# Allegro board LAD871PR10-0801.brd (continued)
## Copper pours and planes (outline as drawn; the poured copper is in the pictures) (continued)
AUD_SPK_L+_C on BOTTOM (solid shape): 80.64,6.48 80.83,6.48 80.83,5.46 79.75,5.46 79.43,5.78 79.43,6.38 78.61,7.21 77.29,7.21 77.17,7.33 77.17,7.78 77.29,7.9 79.21,7.9
AUD_SPK_L- on TOP (solid shape): 93.57,4.62 93.54,4.6 91.32,4.6 91.14,4.77 91.14,5.55 91.21,5.61 93.57,5.61
AUD_SPK_L- on TOP (solid shape): 184.99,10.39 184.99,8.6 184.93,8.53 183.72,8.53 183.6,8.65 183.6,10.31 183.78,10.49 184.89,10.49
AUD_SPK_L- on BOTTOM (solid shape): 183.48,11.25 183.48,10.78 183.8,10.46 184.28,10.46 184.36,10.39 184.36,9.6 184.21,9.45 183.78,9.45 182.99,10.24 182.99,11.24 183.02,11.28 183.46,11.28
AUD_SPK_L-_C on TOP (solid shape): 81.34,8.89 81.34,3.94 81.67,3.61 84.21,3.61 85.81,5.21 87.56,5.21 87.69,5.33 88.86,5.33 88.88,5.35 89.26,5.35 89.72,5.81 90.77,5.81 90.88,5.7 90.88,4.72 90.83,4.67 88.32,4.67 87.42,3.76 86.62,3.76 85.46,2.6 81.08,2.6 80.13,3.56 80.13,8.89 80.26,9.02 81.21,9.02
AUD_SPK_L-_C on BOTTOM (solid shape): 81.27,9.21 81.27,8.45 81.08,8.25 77.27,8.25 77.15,8.38 77.15,8.89 77.27,9.02 78.54,9.02 78.86,9.33 81.15,9.33
AUD_SPK_R+ on TOP (solid shape): 92.38,9.69 92.26,9.58 91.2,9.58 91.09,9.69 91.09,10.91 91.27,11.08 92.38,11.08
AUD_SPK_R+ on TOP (solid shape): 182.05,11.18 182.05,11 181.9,10.85 181.74,10.85 181.39,10.49 181.38,10.49 181.38,10.25 180.57,9.44 180.12,9.44 179.53,10.03 179.53,10.18 180.68,11.33 181.9,11.33
AUD_SPK_R+ on BOTTOM (solid shape): 182.66,12.5 182.66,12.27 182.07,11.68 182.07,10.97 181.57,10.46 181.26,10.46 181.13,10.59 181.13,10.85 181.69,11.4 181.69,11.63 182.58,12.52 182.63,12.52
AUD_SPK_R+_C on TOP (solid shape): 87.69,11.11 87.69,11.05 90.81,11.05 90.95,10.92 90.95,9.66 90.88,9.6 89.91,9.6 89.47,10.04 89.46,10.04 89.41,10.1 85.94,10.1 85.62,10.41 83.75,10.41 82.99,9.65 82.99,4.89 83.11,4.76 83.11,4 82.99,3.87 82.16,3.87 81.84,4.19 81.84,10.16 83.11,11.43 87.37,11.43
AUD_SPK_R+_C on BOTTOM (solid shape): 78.75,5.75 78.75,5.3 79.17,4.89 82.99,4.89 83.11,4.76 83.11,4 83.01,3.9 78.76,3.9 77.17,5.49 77.17,5.68 77.36,5.87 78.63,5.87
AUD_SPK_R- on TOP (solid shape): 93.57,8.25 93.54,8.23 91.2,8.23 91.03,8.39 91.03,9.05 91.23,9.25 93.57,9.25
AUD_SPK_R- on TOP (solid shape): 182.05,10.16 182.05,8.81 181.2,7.96 180.82,7.96 180.14,8.64 180.14,8.83 181.6,10.29 181.92,10.29
AUD_SPK_R- on BOTTOM (solid shape): 182.71,10.97 182.71,10.39 181.69,9.37 181.36,9.37 181.24,9.5 181.24,9.73 182.19,10.69 182.19,10.91 182.2,10.92 182.2,10.96 182.26,11.02 182.65,11.02
AUD_SPK_R-_C on TOP (solid shape): 90.86,9.11 90.86,8.31 90.68,8.13 85.78,8.13 84.51,6.86 83.37,6.86 83.31,6.92 83.31,7.3 84.64,8.64 84.83,8.64 85.38,9.19 90.78,9.19
AUD_SPK_R-_C on BOTTOM (solid shape): 83.5,7.75 84.19,7.75 84.38,7.56 84.38,6.98 84.19,6.79 83.05,6.79 81.91,7.94 81.91,8.32 82.92,8.32
AUD_SPK_R-_C on BOTTOM (solid shape): 77.08,6.86 78.61,6.86 78.73,6.73 78.73,6.35 78.61,6.22 77.34,6.22 77.15,6.03 76.45,6.03 75.75,6.73 75.75,7.24 76.7,7.24
BST2_VGA on BOTTOM (solid shape): 162.36,105.15 162.36,105.02 163.05,104.33 163.06,104.33 163.19,104.2 164.65,104.2 164.65,103.31 163.33,103.31 161.7,104.95 161.49,104.95 161.34,105.1 161.34,105.19 161.39,105.24 162.27,105.24
BST_1.2V on TOP (solid shape): 61.97,20.64 63.43,20.64 63.43,20 61.78,20 60.95,20.83 59.81,20.83 59.81,21.02 61.59,21.02
BST_1.2V_R on TOP (solid shape): 63.43,17.53 63.37,17.46 62.86,17.46 62.79,17.53 62.79,18.29 62.54,18.54 62.54,19.24 63.43,19.24
BST_3V on BOTTOM (solid shape): 31.12,37.52 32.85,37.52 32.92,37.44 32.92,37.34 32.77,37.19 29.87,37.19 29.8,37.25 29.8,38.27 29.87,38.33 30.31,38.33
BST_5V on BOTTOM (solid shape): 42.63,37.69 44.56,37.69 44.61,37.64 44.61,37.49 44.35,37.24 41.46,37.24 41.41,37.29 41.41,38.18 41.46,38.23 42.09,38.23
BST_+1.5VGPU on BOTTOM (solid shape): 132.84,138.68 130.61,138.68 130.61,138.94 131.57,138.94 132.2,139.57 132.84,139.57
BST_+1.5VGPU_R on BOTTOM (solid shape): 133.72,140.08 134.23,139.57 134.23,138.68 133.6,138.68 133.6,139.52 133.22,139.9 133.22,140.53 133.72,140.53
BST_+1VALW on BOTTOM (solid shape): 128.52,123.76 129.85,123.76 129.91,123.7 129.91,123.57 129.85,123.51 127.18,123.51 127.12,123.57 127.12,124.46 127.18,124.52 127.76,124.52
BST_+1VALW_R on BOTTOM (solid shape): 126.42,124.46 126.42,123.62 126.56,123.48 126.71,123.48 126.93,123.25 126.93,122.55 126.36,122.55 126.36,122.94 125.72,123.57 125.72,124.46 125.79,124.52 126.36,124.52
BST_+VCCEOPIO on BOTTOM (solid shape): 38.47,53.28 38.47,52.96 39.36,52.07 39.36,50.36 39.3,50.29 38.47,50.29 38.41,50.36 38.41,52.32 37.59,53.15 37.59,53.28 37.65,53.34 38.41,53.34
BST_R_+VCCEOPIO on BOTTOM (solid shape): 40.38,49.09 40.19,48.89 38.41,48.89 38.41,49.53 38.47,49.59 40.38,49.59
C0_1.0VS_VCCOPCP on BOTTOM (solid shape): 34.4,57.14 34.4,56.48 34.48,56.4 36.36,56.4 36.82,55.94 36.82,54.86 36.76,54.8 36.7,54.8 36.57,54.93 36.57,55.63 36.25,55.94 35.3,55.94 35.11,56.13 35.1,56.13 35.06,56.17 34.13,56.17 33.7,56.6 33.7,57.19 33.71,57.2 34.34,57.2
C1_1.0VS_VCCOPCP on BOTTOM (solid shape): 33.45,57.09 33.46,57.09 33.56,56.98 33.56,56.44 33.68,56.44 34.08,56.05 35.01,56.05 35.36,55.69 36.32,55.69 36.38,55.63 36.38,54.93 36.25,54.8 35.74,54.8 34.92,55.63 34.91,55.63 34.84,55.69 34.03,55.69 33.46,56.26 32.69,56.26 32.6,56.36 32.6,57.07 32.71,57.18 33.35,57.18
CORE_SNUB on TOP (solid shape): 111.75,122.9 111.75,120.4 111.66,120.3 110.58,120.3 110.55,120.33 110.55,123 110.58,123.03 111.63,123.03
CORE_SW on TOP (solid shape): 114.48,122.43 114.48,120.4 114.36,120.27 113.21,120.27 113.09,120.4 113.09,122.55 113.15,122.62 114.29,122.62
CORE_SW on BOTTOM (solid shape): 115.25,122.36 115.25,119.04 113.34,119.04 113.34,120.02 112.45,120.02 112.45,119.05 110.61,119.05 110.61,122.24 111.74,123.37 111.74,123.55 111.8,123.62 113.99,123.62
CPU_B+ on TOP (solid shape): 119.3,128.09 119.3,126.45 119.22,126.36 116.95,126.36 116.93,126.38 116.93,126.62 116.87,126.68 115.07,126.68 115,126.75 115,128.81 114.98,128.83 115.75,129.6 117.79,129.6
CPU_B+ on TOP (solid shape): 109.55,129.66 109.55,127.78 109.29,127.51 109.29,127.35 109.28,127.34 109.26,127.23 109.28,127.13 109.29,127.12 109.29,126.78 109.55,126.51 109.55,125.96 109.5,125.91 108.05,125.91 107.95,126 107.95,129.61 108.11,129.76 109.46,129.76
CPU_B+ on BOTTOM (solid shape): 111.44,131.64 111.44,129.86 109.59,128.02 109.59,126.85 109.91,126.54 110.4,126.54 110.6,126.75 111.31,126.75 111.35,126.79 111.35,127.33 111.38,127.36 114.01,127.36 115.25,128.59 115.25,128.78 116.13,129.67 116.13,130.62 116.33,130.81 117.47,130.81 117.47,129.48 119.21,127.73 119.21,126.38 119.19,126.35 118.6,126.35 118.14,126.81 115.59,126.81 114.6,125.82 112.32,125.82 112.31,125.82 111.41,125.82 111.37,125.85 111.37,126.26 111.26,126.37 110.58,126.37 110.31,126.1 110.31,125.58 110.18,125.45 105.84,125.45 105.53,125.76 105.53,130.17 107.05,131.7 111.37,131.7
CPU_B+ on IN2 (solid shape): outline of 176 points within 107.5,124.27 118.1,129.73
CS_1.2V on TOP (solid shape): 58.73,19.75 58.73,18.48 59.37,17.84 59.37,16.76 58.73,16.76 58.73,17.34 58.54,17.53 58.54,19.74 58.6,19.81 58.67,19.81
DCBAT_CAM on BOTTOM (solid shape): 77.59,168.72 77.97,168.72 78.67,168.02 81.91,168.02 82.48,167.45 82.48,165.54 82.35,165.42 81.72,165.42 81.65,165.48 81.65,166.56 81.15,167.07 78.29,167.07 77.5,167.86 77.5,167.99 77.44,168.05 75.84,168.05 75.75,168.14 75.75,168.67 75.76,168.68 75.75,168.69 75.75,168.78 75.88,168.91 77.4,168.91
DCBATOUT_LCD on BOTTOM (solid shape): outline of 138 points within 74.8,160.56 81.46,168.02
EC_AGND on IN1 (solid shape): outline of 112 points within 182.55,57.98 186.62,66.06
EN_0.6VSP on TOP (solid shape): 55.56,23.24 56.44,22.35 56.44,21.65 56.66,21.44 57.46,21.44 57.51,21.39 57.52,21.39 57.52,21.27 57.46,21.21 56.38,21.21 56.06,21.53 56.06,22.16 55.43,22.8 55.05,22.8 55.05,24.26 55.56,24.26
EN_1.2V on TOP (solid shape): 55.56,21.59 56.13,21.02 57.46,21.02 57.52,20.95 57.52,20.89 57.46,20.83 55.75,20.83 55.56,21.02 55.05,21.02 55.05,22.48 55.56,22.48
EN_1.8VALW on BOTTOM (solid shape): 174.79,26.86 174.79,26.31 175.13,25.97 175.76,25.97 175.82,25.91 175.82,25.46 175.76,25.4 174.3,25.4 174.27,25.43 174.27,25.93 174.05,26.16 173.28,26.16 173.22,26.23 173.22,26.67 173.28,26.73 174.05,26.73 174.24,26.92 174.72,26.92
EN_2.5V on BOTTOM (solid shape): 60.64,29.46 60.64,29.08 60.51,28.96 56.89,28.96 56.89,29.46 57.02,29.59 60.51,29.59
EN_+1VALW on BOTTOM (solid shape): 133.28,127.17 133.11,127.01 133.11,125.5 132.93,125.32 132.17,125.32 132.14,125.35 132.14,125.48 132.14,125.48 132.14,125.53 132.33,125.72 132.33,126.56 131.69,127.19 131.69,127.76 133.28,127.76
EN_+VCCEOPIO on BOTTOM (solid shape): 37.01,56.58 37.33,56.26 37.33,54.86 37.27,54.8 37.14,54.8 37.08,54.86 37.08,55.88 36.43,56.53 34.59,56.53 34.53,56.59 34.53,57.05 34.57,57.09 37.01,57.09
FAN_VCC1 on BOTTOM (solid shape): 100.22,146.02 100.22,137.66 99.87,137.66 99.48,137.82 99.21,137.5 99.17,137.44 99.1,137.41 97.08,137.41 94.37,134.7 93.12,134.7 92.78,135.04 91.92,137.16 91.92,137.28 92.14,137.51 92.37,137.51 92.49,137.38 92.99,136.39 93.24,136.14 94.28,136.14 97.03,138.89 98.75,138.89 99.07,139.22 99.07,145.57 98.76,145.89 97.17,145.89 97.04,146.02 97.04,146.46 97.23,146.65 99.58,146.65
FB_1.2V on TOP (solid shape): 56.57,23.24 57.46,22.35 57.46,21.65 56.7,21.65 56.64,21.72 56.64,22.54 56.06,23.11 56.06,24.38 55.81,24.64 55.05,24.64 55.05,25.21 55.81,25.21 56,25.4 56.57,25.4
GPU_B+ on TOP (solid shape): 62.42,47.39 62.42,45.82 60.7,44.11 60.7,41.44 60.99,41.15 64.51,41.15 64.83,40.83 66.68,40.83 66.74,40.77 69.84,40.77 69.97,40.64 69.97,38.11 69.92,37.94 69.95,37.77 69.7,37.51 59.94,37.51 59.94,37.5 59.94,36.97 59.49,36.97 59.49,37.5 58.74,37.5 58.74,36.97 58.29,36.97 58.29,37.5 58.28,37.5 58.28,37.51 57.59,37.51 57.59,39.31 57.97,39.69 57.97,43.39 54.67,46.69 54.67,47.24 54.84,47.42 59.03,47.42 59.12,47.51 62.3,47.51
GPU_B+ on BOTTOM (solid shape): outline of 104 points within 54.51,36.44 70.9,47.51
GT_SNUB1 on TOP (solid shape): 71.24,47.24 71.24,44.95 71.14,44.84 68.9,44.84 68.78,44.97 68.78,47.24 68.88,47.34 71.13,47.34
GT_SNUB2 on TOP (solid shape): 60.2,53.77 60.2,51.74 59.47,51 58.4,51 58.25,51.16 58.25,53.72 58.4,53.87 60.1,53.87
GT_SW1 on TOP (solid shape): 67.32,47.25 67.32,44.38 67.19,44.25 66.33,44.25 66.22,44.36 66.22,47.32 66.27,47.37 67.2,47.37
GT_SW1 on BOTTOM (solid shape): 68.07,47.46 68.07,46.49 68.95,46.49 68.95,47.45 68.98,47.47 70.81,47.47 70.99,47.29 70.99,44.58 69.65,43.24 69.65,43.07 69.51,42.93 67.62,42.93 67.54,43 67.54,43.95 67.31,44.19 65.91,44.19 65.53,44.57 65.53,47.12 65.92,47.51 68.01,47.51
GT_SW2 on TOP (solid shape): 57.46,54.08 57.46,51.97 55.76,51.97 55.63,52.1 55.63,54.1 55.82,54.29 57.24,54.29
GT_SW2 on BOTTOM (solid shape): 57.82,53.25 58.63,53.25 58.63,54.23 61.99,54.23 62.16,54.06 62.16,49.9 62.01,49.75 60.06,49.75 60.03,49.78 60.03,50.98 59.5,51.5 58.16,51.5 58.16,51.51 56.11,51.51 55.56,52.07 55.56,54.07 55.71,54.23 57.82,54.23
HDMI_PLL_GND on TOP (solid shape): 25.65,77.28 25.65,74.17 25.9,73.91 28,73.91 28.5,74.42 29.46,74.42 29.71,74.17 29.71,73.41 29.33,73.02 26.79,73.02 25.58,71.82 25.01,71.82 24.95,71.88 24.95,77.28 25.08,77.41 25.52,77.41
IR_GND on BOTTOM (solid shape): 93.5,166.45 93.5,163.07 93.88,162.69 93.88,160.66 93.83,160.6 92.87,160.6 92.59,160.88 92.59,166.4 92.74,166.55 93.4,166.55
KB_BL_CTRL# on TOP (solid shape): 189.16,126.94 189.16,126.36 189.73,125.79 190.74,125.79 190.75,125.8 190.77,125.77 191.52,125.77 192.55,124.74 192.55,124.49 192.48,124.43 189.32,124.43 188.08,125.67 188.08,126.05 187.64,126.49 187.64,126.94 187.89,127.19 188.91,127.19
LANGND on BOTTOM (solid shape): 18.4,162.52 18.4,161.34 18.28,161.23 16.06,161.23 16,161.16 15.11,161.16 15.11,162.18 15.53,162.6 18.32,162.6
LCDVDD on BOTTOM (solid shape): 81.29,156.35 82.66,156.35 82.92,156.09 82.92,155.52 82.67,155.28 79.63,155.28 79.43,155.47 79.43,156.34 79.62,156.53 81.11,156.53
LCDVDD_LCD on TOP (solid shape): 80.12,158.11 81.37,158.11 81.64,157.84 81.64,156.92 80.84,156.11 79.53,156.11 79.37,156.27 79.37,156.46 78.67,157.16 78.67,158.18 78.8,158.31 79.93,158.31
LCDVDD_LCD on BOTTOM (solid shape): 84.45,166.37 84.45,165.42 82.85,163.82 82.81,163.85 82.27,163.81 82.4,163.28 82.45,163.2 82.41,163.11 82.26,162.73 82.56,162.46 82.61,162.46 82.61,160.53 81.62,159.54 81.62,158.9 81.26,158.54 81.26,158.22 81.48,158 81.62,158 81.62,157.38 81.39,157.15 79.51,157.15 79.38,157.28 79.38,160.55 79.53,160.7 79.53,161.09 80.7,162.26 80.83,162.53 80.7,162.81 80.7,164.06 81.4,164.77 81.48,164.8 81.55,164.76 81.97,164.68 82.17,165.05 82.2,165.13 82.27,165.16 82.86,165.16 83.11,165.42 83.11,166.37 83.24,166.5 84.32,166.5
LDO_+1.5VGPU on TOP (solid shape): 128.83,140.02 128.71,139.89 127.88,139.89 127.76,140.02 127.76,140.84 127.88,140.97 128.83,140.97
LDO_+1.5VGPU on BOTTOM (solid shape): 129.09,140.46 129.09,139.13 128.96,139 128.45,139 128.33,139.13 128.33,139.51 127.88,139.95 127.88,140.46 128.07,140.65 128.9,140.65
LDO_+1VALW on BOTTOM (solid shape): 132.58,122.81 134.55,122.81 134.55,122.17 131.76,122.17 131.34,122.59 131.34,123.34 131.44,123.44 131.95,123.44
LG1_VGA on TOP (solid shape): 170.61,104.67 170.61,103.8 170.48,103.67 169.01,103.67 168.74,103.94 168.74,104.69 168.93,104.88 170.4,104.88
LG1_VGA on BOTTOM (solid shape): 170.04,109.07 170.04,108.1 169.92,107.98 168.81,107.98 168.74,108.05 168.74,109.04 168.9,109.2 169.91,109.2
LG1_VGA on BOTTOM (solid shape): 163.88,107.83 163.88,107.52 163.79,107.43 161.39,107.43 161.34,107.49 161.34,107.59 161.39,107.64 162.68,107.64 162.93,107.89 163.82,107.89
LG1_VGA on IN2 (solid shape): 170.6,109.87 170.6,107.4 170.95,107.05 170.95,103.86 170.66,103.57 169.96,103.57 169.78,103.75 169.78,106.47 169.35,106.9 164.49,106.9 163.95,107.45 162.9,107.45 162.82,107.54 162.82,107.79 162.93,107.9 168.66,107.9 168.74,107.99 168.74,109.49 168.73,109.5 168.73,110.07 168.9,110.24 170.23,110.24
LG2_VGA on TOP (solid shape): 170.11,98.64 170.11,97.7 169.95,97.53 169,97.53 168.74,97.79 168.74,98.75 168.88,98.89 169.85,98.89
LG2_VGA on BOTTOM (solid shape): 170.04,103.16 170.04,102.11 169.89,101.96 168.83,101.96 168.74,102.05 168.74,103.14 168.86,103.27 169.93,103.27
LG2_VGA on BOTTOM (solid shape): 162.48,106.44 162.66,106.33 162.86,106.34 162.87,106.34 163.81,106.34 163.91,106.24 163.91,106.01 163.78,105.89 162.94,105.89 162.59,106.24 161.39,106.24 161.34,106.29 161.34,106.39 161.39,106.44
LG2_VGA on IN2 (solid shape): 165.46,105.99 169.22,105.99 169.22,105.98 169.53,105.67 169.53,103.48 169.98,103.02 169.98,97.58 169.94,97.54 168.99,97.54 168.84,97.69 168.84,105.03 168.65,105.23 165.03,105.23 164.37,105.89 162.94,105.89 162.84,105.99 162.84,106.24 162.94,106.34 163.31,106.34 163.46,106.5 164.95,106.5
LG_1.2V on TOP (solid shape): 60.64,18.86 60.64,18.41 60.51,18.29 60.32,18.29 59.68,18.92 59.37,18.92 59.3,18.99 59.3,19.75 59.37,19.81 59.68,19.81
LG_1.2V on BOTTOM (solid shape): 68.51,15.41 68.51,14.35 68.42,14.26 67.45,14.26 67.3,14.41 67.3,15.34 67.39,15.43 67.56,15.43 67.56,15.43 68.48,15.43
LG_1.2V on IN2 (solid shape): 60.89,18.48 60.89,17.46 60.32,17.46 60.19,17.59 60.19,18.16 59.68,18.67 59.68,19.11 59.81,19.24 60.13,19.24
LG_1.2V on IN2 (solid shape): 67.94,15.3 67.94,14.29 67.49,13.84 66.67,13.84 66.35,14.16 66.35,14.48 66.41,14.54 66.54,14.54 67.43,15.43 67.81,15.43
LGATE_CHG on TOP (solid shape): 125.41,162.12 125.41,161.29 125.28,161.16 124.39,161.16 124.14,161.42 124.14,162.12 124.26,162.24 125.28,162.24
LGATE_CHG on BOTTOM (solid shape): 114.14,158.72 114.14,158.45 114.04,158.35 111.75,158.35 111.7,158.39 111.7,158.55 112.94,158.55 113.19,158.8 114.06,158.8
LGATE_CHG on IN1 (solid shape): 125.41,162.18 125.41,161.67 125.15,161.42 122.99,161.42 122.99,162.43 125.15,162.43
LGATE_CHG on IN1 (solid shape): 116.26,159 114.67,159 114.04,158.37 113.15,158.37 113.02,158.5 113.02,158.69 113.21,158.88 113.59,158.88 114.36,159.64 114.61,159.64 114.99,160.02 116.26,160.02
LP#_+VCCEOPIO on BOTTOM (solid shape): 37.9,57.02 37.9,54.93 37.84,54.86 37.65,54.86 37.59,54.93 37.59,56.26 37.27,56.58 37.27,57.02 37.33,57.09 37.84,57.09
LX1_VGA on TOP (solid shape): 179.51,114.17 179.51,104.48 179.1,104.07 170.95,104.07 170.74,104.29 170.74,104.98 170.5,105.22 170.5,109.06 170.79,109.35 175.32,109.35 175.7,109.73 175.7,110.36 175.44,110.62 174.43,110.62 174.05,111 174.05,114.81 174.3,115.06 178.62,115.06
LX1_VGA on BOTTOM (solid shape): 164.97,108.46 164.97,107.95 164.9,107.89 164.39,107.89 164.2,108.08 162.91,108.08 162.68,107.84 161.39,107.84 161.34,107.89 161.34,107.99 161.39,108.04 162.49,108.04 162.96,108.52 163.44,108.52 163.51,108.58 164.84,108.58
LX1_VGA on BOTTOM (solid shape): 179.51,113.79 179.51,109.16 179.09,108.74 177.78,108.74 177.74,108.7 177.74,107.94 177.77,107.91 179.2,107.91 179.5,107.62 179.5,104.5 179.07,104.07 170.86,104.07 170.72,104.2 170.72,104.69 170.5,104.91 170.5,109.01 170.72,109.22 175.06,109.22 175.55,109.71 175.55,110.48 176.12,111.05 176.12,111.29 175.84,111.57 175.49,111.57 175.27,111.34 174.11,111.34 173.91,111.55 173.91,114.83 174.13,115.06 178.24,115.06
LX1_VGA on IN2 (solid shape): 176.73,112.17 176.73,111.41 176.61,111.28 172.8,111.28 172.8,112.29 176.61,112.29
LX1_VGA on IN2 (solid shape): 164.74,109.62 164.74,108.09 164.68,108.03 163.74,108.03 163.64,108.04 163.55,108.03 163.14,108.03 163.04,108.05 162.95,108.03 162.88,108.03 162.82,107.98 162.66,107.98 162.56,108.07 162.56,108.53 162.6,108.61 162.7,108.63 162.89,108.62 163.06,108.71 163.09,108.73 163.13,108.71 163.74,108.97 163.13,109.22 163.09,109.21 163.06,109.22 162.86,109.32 162.64,109.28 162.63,109.27 162.56,109.27 162.56,109.35 162.72,109.51 162.72,109.74 162.72,109.75 164.61,109.75
LX2_VGA on TOP (solid shape): 179.51,103.12 179.51,95 179.13,94.61 174.61,94.61 174.31,94.91 174.31,97.12 173.48,97.95 170.66,97.95 170.47,98.13 170.47,102.85 171.13,103.5 179.13,103.5
LX2_VGA on BOTTOM (solid shape): 162.88,105.76 164.37,105.76 164.4,105.73 164.9,105.73 165.11,105.52 165.11,104.74 165.05,104.68 164.19,104.68 163.67,105.2 163.45,105.2 163.35,105.3 162.98,105.3 162.45,105.83 161.39,105.83 161.34,105.89 161.34,105.99 161.39,106.04 162.6,106.04
LX2_VGA on BOTTOM (solid shape): 179.44,103 179.44,100.38 179.16,100.1 177.77,100.1 177.75,100.08 177.75,99.32 177.8,99.27 179.12,99.27 179.51,98.88 179.51,95 178.87,94.36 175.66,94.36 175.35,94.05 175.35,93.6 175.09,93.34 174.15,93.34 173.91,93.58 173.91,97.57 173.48,98.01 170.56,98.01 170.48,98.09 170.48,102.86 171.13,103.5 178.93,103.5
LX2_VGA on IN1 (solid shape): 176.73,103.48 176.73,102.47 176.54,102.29 174.86,102.29 174.76,102.38 174.76,103.56 174.9,103.7 176.51,103.7
LX2_VGA on IN1 (solid shape): 164.89,105.16 164.9,105.16 164.9,104.4 164.57,104.4 163.81,105.16 163.62,105.16 163.49,105.29 162.93,105.29 162.84,105.38 162.84,105.66 162.93,105.75 164.3,105.75
LX_1.2V on TOP (solid shape): 60.64,20.13 60.64,19.88 62.41,18.1 62.41,17.53 61.84,17.53 61.84,17.91 59.75,20 59.75,20.13 59.81,20.19 60.57,20.19
LX_1.2V on BOTTOM (solid shape): 74.61,24.26 74.61,16.13 74.1,15.62 67.49,15.62 67.3,15.81 67.3,16.57 67.43,16.7 70.92,16.7 71.37,17.14 71.37,19.77 72.32,20.73 72.32,24.26 72.45,24.38 74.48,24.38
LX_1.2V on IN2 (solid shape): 67.81,16.57 67.81,15.75 67.68,15.62 67.3,15.62 67.11,15.81 66.35,15.81 66.35,16.57 66.48,16.7 67.68,16.7
LX_1.2V on IN2 (solid shape): 61.27,19.24 61.46,19.24 62.1,18.61 62.1,18.29 61.4,18.29 61.21,18.48 61.21,18.54 60.25,19.49 60.25,19.75 60.38,19.88 60.64,19.88
LX_1.8VALW on BOTTOM (solid shape): 173.86,29.97 173.86,27.5 173.54,27.18 172.71,27.18 172.46,26.92 172.46,26.23 172.4,26.16 171.76,26.16 171.7,26.23 171.7,26.73 171.13,27.3 167.57,27.3 167.57,29.02 167.82,29.27 169.98,29.27 170.87,30.16 173.67,30.16
LX_3V on BOTTOM (solid shape): 32.87,40.49 32.94,40.46 33.01,40.44 33.03,40.44 33.25,40.21 33.25,39.45 33.2,39.4 32.98,39.4 32.93,39.45 32.29,39.45 32.24,39.5 32.24,40.36 32.37,40.49
LX_3V on BOTTOM (solid shape): 33.76,37.16 33.76,36.27 33.76,36.27 33.76,34.57 33.94,34.39 35.11,34.39 35.19,34.32 35.19,32.59 35.06,32.46 28.17,32.46 27.87,32.77 27.87,35.05 28,35.18 28.82,35.18 29.46,35.81 29.46,36.96 29.52,37.02 29.71,37.02 29.72,37.03 32.82,37.03 33.05,37.26 33.66,37.26
LX_5V on BOTTOM (solid shape): 44.94,40.43 44.94,39.62 44.86,39.55 44.66,39.55 44.58,39.62 43.95,39.62 43.8,39.78 43.8,40.49 44.02,40.72 44.66,40.72
LX_5V on BOTTOM (solid shape): 45.42,37.34 45.42,34.71 46.22,33.91 47.94,33.91 48.04,33.81 48.04,32.23 47.94,32.13 41.11,32.13 40.82,32.42 40.82,35.81 41.01,36 41.01,36.66 41.33,36.98 44.3,36.98 44.74,37.41 45.35,37.41
LX_+1.5VGPU on TOP (solid shape): 131.25,139.7 131.25,136.08 131.06,135.89 130.49,135.89 130.36,136.02 130.36,139.7 130.55,139.89 131.06,139.89
LX_+1.5VGPU on TOP (solid shape): 128.01,143.88 128.01,141.86 127.88,141.73 126.68,141.73 126.36,142.05 126.36,143.75 126.73,144.12 127.77,144.12
LX_+1.5VGPU on BOTTOM (solid shape): 128.53,143.45 132.01,143.45 132.52,142.94 132.52,140.84 132.84,140.53 132.84,140.02 132.77,139.95 131.69,139.95 131.12,139.38 130.68,139.38 130.3,139 129.79,139 129.72,139.06 129.72,139.83 129.79,139.89 130.8,139.89 131.12,140.21 131.12,140.97 130.99,141.1 127.25,141.1 126.36,141.99 126.36,143.78 126.7,144.12 127.86,144.12
LX_+1VALW on TOP (solid shape): 129.72,127.05 129.72,122.66 129.59,122.53 129.12,122.53 128.81,122.83 128.81,127.03 128.98,127.19 129.58,127.19
LX_+1VALW on BOTTOM (solid shape): 130.23,126.62 130.23,125.73 130.17,125.67 130.04,125.67 129.24,126.47 129.24,127.08 129.36,127.19 129.66,127.19
LX_+1VALW on BOTTOM (solid shape): 130.68,123.38 130.68,122.43 130.74,122.36 130.74,117.54 130.68,117.47 128.61,117.47 128.53,117.55 128.53,120.45 127.95,121.03 125.66,121.03 125.66,122.11 126.93,122.11 127.31,122.49 127.31,123.13 129.72,123.13 130.04,123.44 130.61,123.44
MCT on TOP (solid shape): 16.88,171.26 16.88,169.48 16.76,169.35 15.87,169.35 15.74,169.48 15.74,171.26 15.87,171.39 16.76,171.39
MCT on BOTTOM (solid shape): 18.34,165.25 18.34,163.96 18.28,163.89 16.06,163.89 15.93,164.02 15.93,164.91 16.29,165.27 18.33,165.27
MCT on BOTTOM (solid shape): 16.88,171.26 16.88,169.48 16.76,169.35 15.87,169.35 15.74,169.48 15.74,171.26 15.87,171.39 16.76,171.39
MCT on IN1 (solid shape): 17.52,170.56 17.52,169.54 17.46,169.48 16.44,169.48 16.38,169.54 16.38,170.5 16.57,170.69 17.39,170.69
MCT on IN1 (solid shape): 17.27,165.54 17.27,164.97 16.88,164.59 16.88,164.08 16.69,163.89 16.06,163.89 15.87,164.08 15.87,164.97 16.69,165.8 17.01,165.8
ODD_PWR_5V on TOP (solid shape): 156.5,83.2 156.5,81.12 156.34,80.96 155,80.96 154.86,81.1 154.86,81.1 154.64,81.26 154.37,81.21 153.88,81.21 153.68,81.41 153.68,81.83 153.79,81.94 154.19,81.94 154.22,81.98 154.22,83.24 154.74,83.76 155.94,83.76
ODD_PWR_5V on TOP (solid shape): 166.81,43.88 166.81,43.35 167.87,42.29 177.16,42.29 177.35,42.48 178.81,42.48 179,42.29 179,41.52 178.9,41.27 179,41.03 179,38.61 178.94,38.54 178.17,38.54 178.11,38.61 178.11,40.07 177.92,40.26 165.29,40.26 164.88,40.66 164.88,43.69 165.26,44.06 166.63,44.06
ODD_PWR_5V on IN1 (solid shape): outline of 536 points within 153.54,42.13 166.81,82.8
PHASE_CHG on TOP (solid shape): 123.37,164.21 123.37,161.99 123.82,161.54 123.82,158.88 123.12,158.18 123.12,157.35 122.93,157.16 121.53,157.16 121.34,157.35 121.34,158.24 121.21,158.37 120.98,158.37 120.97,158.37 120.85,158.39 120.73,158.37 120.72,158.37 120.45,158.37 120.33,158.5 120.33,163.51 121.21,164.4 123.18,164.4
PHASE_CHG on BOTTOM (solid shape): 123.5,164.08 123.5,158.62 123.06,158.18 119.56,158.18 119.18,158.56 119.18,162.62 120.9,164.34 123.25,164.34
PHASE_CHG on BOTTOM (solid shape): 115.4,157.63 115.4,157.09 115.34,157.03 114.74,157.03 114.29,157.48 114.29,157.49 114.14,157.65 114.13,157.65 114.08,157.7 113.18,157.7 112.93,157.95 111.65,157.95 111.61,157.99 111.61,158.09 111.67,158.15 114.88,158.15
PHASE_CHG on IN1 (solid shape): 121.47,158.75 121.47,158.11 120.96,157.61 117.53,157.61 117.53,158.62 120.07,158.62 120.33,158.88 121.34,158.88
PHASE_CHG on IN1 (solid shape): 115.75,157.61 114.36,157.61 114.29,157.67 113.15,157.67 113.02,157.8 113.02,158.05 113.15,158.18 114.17,158.18 114.61,158.62 115.75,158.62
REGOUT on TOP (solid shape): 55.01,173.77 54.88,173.64 54.01,173.64 53.31,172.94 53.23,172.94 53.06,172.78 53.05,172.78 53.05,172.76 52.97,172.69 52.97,171.41 51.85,170.29 50.95,170.29 50.88,170.36 50.88,170.49 50.98,170.59 50.98,171.48 51.19,171.69 51.19,173.07 51.58,173.45 51.58,174.4 51.7,174.53 55.01,174.53
RING2 on TOP (solid shape): 184.3,22.56 184.3,21.62 184.21,21.53 182.3,21.53 181.79,22.03 181.79,22.61 181.86,22.67 184.19,22.67
RING2 on BOTTOM (solid shape): 183.24,22.55 183.24,21.65 183.08,21.48 183.08,18.95 183.03,18.9 182.89,18.9 182.86,18.93 182.86,19.96 182.45,20.37 182.44,20.43 182.43,20.48 182.43,22.61 182.55,22.73 183.06,22.73
RING2_R on TOP (solid shape): 192.49,24.94 192.49,24.64 192.31,24.46 191.32,24.46 191.24,24.38 191.24,24.16 191.32,24.08 192.36,24.08 192.49,23.95 192.49,23.62 192.33,23.47 190.59,23.47 188.74,21.62 184.99,21.62 184.99,22.64 187.61,22.64 189.3,24.33 190.07,24.33 190.81,25.07 192.36,25.07
SA_SNUB on BOTTOM (solid shape): 123.63,122.62 124.77,122.62 124.77,121.98 123.95,121.16 122.42,121.16 122.42,122.81 123.44,122.81
SA_SW on BOTTOM (solid shape): 121.47,130.3 121.47,129.6 120.9,129.03 119.56,129.03 119.56,129.98 119.86,130.28 121.13,130.28 121.21,130.37 121.41,130.37
SA_SW on BOTTOM (solid shape): 122.41,123.24 121.15,121.98 121.15,121.28 121.47,120.97 123.25,120.97 124.01,120.21 124.01,118.43 123.69,118.11 121.6,118.11 121.6,119.06 120.71,119.06 120.71,118.11 120.64,118.05 118.8,118.05 118.29,118.55 118.29,121.49 119.68,122.87 120.52,122.87 121.34,123.69 121.34,126.24 122.41,126.24
SLEEVE on TOP (solid shape): 184.27,24.45 184.27,23.05 182.81,23.05 182.68,22.92 181.79,22.92 181.79,23.5 182.43,23.5 183,24.07 183,24.51 183.13,24.64 184.08,24.64
SLEEVE on BOTTOM (solid shape): 184.21,24.44 184.21,23.6 184.21,23.6 184.21,21.24 184.12,21.16 184.08,21.11 183.6,20.62 183.6,20.56 183.6,20.04 183.47,19.91 183.47,18.95 183.42,18.9 183.29,18.9 183.24,18.95 183.24,21.47 183.4,21.62 183.4,23.77 182.99,24.19 182.99,24.51 183.14,24.66 183.98,24.66
SLEEVE_R on TOP (solid shape): 192.51,26.97 192.51,26.59 192.41,26.49 191.29,26.49 191.22,26.42 191.22,26.14 191.29,26.06 192.39,26.06 192.51,25.93 192.51,25.6 192.39,25.48 190.86,25.48 190.01,24.62 189.08,24.62 187.48,23.02 184.99,23.02 184.99,23.97 184.96,23.97 184.94,24.03 185.29,24.38 186.75,24.38 188.17,25.81 189.8,25.81 191.06,27.08 192.41,27.08
SNUB_+1.5VGPU on TOP (solid shape): 131.95,142.88 130.93,142.88 130.68,142.62 130.68,141.86 129.66,141.86 129.66,143.51 131.95,143.51
SNUB_+1VALW on BOTTOM (solid shape): 127.31,117.35 127.25,117.28 126.36,117.28 125.66,117.98 125.66,119.38 125.72,119.44 127.31,119.44
SW_VCCEOPIO on BOTTOM (solid shape): 43.94,56.39 42.16,54.61 42.16,52.39 40.44,50.67 40.44,50.04 40.38,49.97 39.81,49.97 39.74,50.04 39.74,52.32 38.47,53.59 37.39,53.59 37.39,53.85 38.47,53.85 39.11,54.48 39.11,55.88 39.24,56.01 40.82,56.01 42.92,58.1 42.92,59.63 43.94,59.63
TON_1.2V on TOP (solid shape): 55.68,20.64 57.46,20.64 57.52,20.57 57.52,20.51 57.46,20.45 56.32,20.45 56,20.13 55.05,20.13 55.05,20.7 55.62,20.7
TP_VDD on IN1 (solid shape): 58.43,77.79 58.52,77.73 58.51,77.62 58.78,77.04 59.06,77.62 59.04,77.73 59.13,77.79 60.19,77.79 60.32,77.66 60.32,72.83 58.75,71.27 58.29,71.23 58.25,70.77 57.4,69.91 55.94,69.91 55.56,70.29 55.56,77.41 55.94,77.79
TPAN_VDD on BOTTOM (solid shape): 101.53,166.31 101.53,164.85 101.4,164.72 100.32,164.72 100.13,164.91 100.13,166.37 100.26,166.5 101.34,166.5
TPAN_VDD on BOTTOM (solid shape): 98.61,154.69 98.61,154.21 98.6,154.2 98.57,154.05 98.6,153.9 98.61,153.89 98.61,153.64 98.6,153.63 98.57,153.48 98.6,153.33 98.61,153.32 98.61,153.07 98.6,153.06 98.57,152.91 98.6,152.76 98.61,152.75 98.61,152.43 98.6,152.42 98.57,152.27 98.6,152.12 98.61,152.11 98.61,151.51 97.34,150.24 95.18,150.24 95.05,150.37 95.05,153.82 95.72,154.48 96.18,154.48 96.64,154.94 98.35,154.94
TPAN_VDD on IN1 (solid shape): outline of 112 points within 95.74,151.31 101.53,165.23
TPAN_VDD_F on BOTTOM (solid shape): 94.44,154.67 94.44,150.19 94.39,150.14 90.84,150.14 90.18,150.8 90.18,151.41 91.65,151.41 91.65,151.36 91.66,151.3 91.67,151.25 91.7,151.21 91.73,151.16 91.76,151.12 91.8,151.09 91.85,151.06 91.9,151.04 91.95,151.03 92,151.03 92.06,151.03 92.11,151.04 92.16,151.06 92.21,151.09 92.25,151.12 92.28,151.16 92.31,151.21 92.34,151.25 92.35,151.3 92.36,151.36 92.36,151.41 92.35,151.46 92.34,151.51 92.31,151.56 92.28,151.61 92.25,151.65 92.21,151.68 92.16,151.71 92.11,151.72 92.06,151.74 92,151.74 91.95,151.74 91.9,151.72 91.85,151.71 91.8,151.68 91.76,151.65 91.73,151.61 91.7,151.56 91.67,151.51 91.66,151.46 91.65,151.41 90.18,151.41 90.18,152.96 90.32,153.11 91.01,153.11 91.29,153.39 91.29,154.9 91.37,154.98 94.13,154.98
UG1_VGA on BOTTOM (solid shape): 175.38,110.64 175.38,109.77 175.15,109.54 174.2,109.54 174.06,109.68 174.06,110.66 174.14,110.75 175.27,110.75
UG1_VGA on BOTTOM (solid shape): 163.63,109.09 163.63,108.84 163.51,108.71 162.93,108.71 162.46,108.23 161.39,108.23 161.34,108.29 161.34,108.39 161.39,108.44 162.28,108.44 162.55,108.71 162.55,109.1 162.67,109.22 162.95,109.22 163.11,109.17 163.27,109.22 163.51,109.22
UG1_VGA on IN1 (solid shape): 175.7,110.62 175.7,109.85 175.69,109.85 175.69,109.76 175.44,109.51 172.75,109.51 172.65,109.61 172.65,110.74 175.57,110.74
UG1_VGA on IN1 (solid shape): 165.09,109.72 165.09,109.25 164.96,109.12 164,109.12 163.86,108.99 163.86,108.82 163.72,108.68 163.69,108.68 163.61,108.69 163.52,108.67 162.86,108.67 162.82,108.7 162.15,108.7 162,108.85 162,109.69 162.08,109.91 162.02,110.13 162.18,110.29 164.51,110.29
UG2_VGA on BOTTOM (solid shape): 176.65,93.85 176.65,93.41 175.29,92.04 174.18,92.04 174.01,92.21 174.01,92.75 174.22,92.96 175.19,92.96 175.52,93.29 175.52,93.84 175.73,94.04 176.46,94.04
UG2_VGA on BOTTOM (solid shape): 162.94,105.15 163.21,105.15 163.39,104.97 163.63,104.97 163.78,104.82 163.78,104.56 163.65,104.44 163.29,104.44 163.28,104.44 163.19,104.44 162.76,104.87 162.76,104.96 162.28,105.44 161.39,105.44 161.34,105.49 161.34,105.59 161.39,105.64 162.45,105.64
UG2_VGA on IN1 (solid shape): 176.65,94.11 176.65,93.66 176.52,93.54 175.32,93.54 174.94,93.92 174.94,94.81 175.95,94.81
UG2_VGA on IN1 (solid shape): 164.38,104.12 164.38,103.45 163.36,103.45 163.36,104.02 162.79,104.59 162.79,105.02 162.92,105.15 163.35,105.15
UG_1.2V on TOP (solid shape): 61.78,19.81 61.78,19.62 61.65,19.49 61.33,19.49 60.83,20 60.83,20.26 60.64,20.45 59.81,20.45 59.81,20.64 60.95,20.64
UG_1.2V on BOTTOM (solid shape): 68.49,18.25 68.49,17.73 68.46,17.7 67.92,17.7 67.68,17.46 67.49,17.46 67.37,17.59 67.37,18.41 67.56,18.61 68.13,18.61
UG_1.2V on IN2 (solid shape): 67.87,18.48 67.87,17.59 67.75,17.46 66.92,17.46 66.73,17.65 66.73,18.41 67.3,18.41 67.49,18.61 67.75,18.61
UG_1.2V on IN2 (solid shape): 61.65,20.07 62.48,20.07 62.92,19.62 62.92,19.11 62.29,19.11 61.91,19.49 61.33,19.49 60.83,20 60.83,20.38 60.89,20.45 61.27,20.45
UGATE_CHG on TOP (solid shape): 118.26,158.03 118.26,156.9 118.2,156.84 113.34,156.84 113.02,157.16 113.02,157.42 113.15,157.54 114.55,157.54 115.13,158.13 118.15,158.13
UGATE_CHG on BOTTOM (solid shape): 113.06,157.52 114.08,157.52 114.16,157.44 114.16,157.15 114.07,157.06 113.19,157.06 112.69,157.55 111.67,157.55 111.63,157.59 111.63,157.72 111.67,157.75 112.83,157.75
USB20_VCCA on TOP (solid shape): outline of 99 points within 189.03,23.1 198.6,36.07
USB20_VCCA on BOTTOM (solid shape): 199.52,25.14 199.52,23.52 199.71,23.33 199.71,21.93 199.63,21.86 196.36,21.86 195.79,22.43 195.15,22.43 195.07,22.52 195.07,25.11 195.26,25.31 199.35,25.31
USB30_VCCC on TOP (solid shape): 24.82,44.32 24.82,43.43 23.84,42.45 14.94,42.45 14.24,43.15 14.24,43.72 14.37,43.85 14.37,44.67 14.91,45.21 23.93,45.21
USB30_VCCC on BOTTOM (solid shape): 24.44,44.7 25.52,44.7 25.9,44.32 25.9,43.37 25.2,42.67 23.04,42.67 22.74,42.98 18.08,42.98 17.96,42.86 14.6,42.86 14.22,43.24 14.22,43.81 15.41,45.01 24.14,45.01
VL on BOTTOM (solid shape): 48.97,37.61 48.97,36.65 48.96,36.63 47.9,36.63 47.12,37.41 46.89,37.41 46.82,37.49 46.82,37.64 46.87,37.69 48.89,37.69
VTTREF_1.2V on TOP (solid shape): 58.35,22.1 58.29,22.03 58.16,22.03 58.1,22.1 58.1,23.62 57.78,23.94 57.78,24.45 58.35,24.45
N17237617 on TOP (solid shape): 125.02,151.13 124.52,150.62 120.77,150.62 120.71,150.69 120.71,156.59 120.77,156.65 122.93,156.65 123.37,157.1 123.37,157.92 123.56,158.11 125.02,158.11
N17237617 on BOTTOM (solid shape): 124.77,156.78 124.77,152.56 124.7,152.49 121.16,152.49 121.08,152.57 121.08,153.15 121.6,153.15 121.6,153.85 121.08,153.85 121.08,154.35 121.6,154.35 121.6,155.05 121.08,155.05 121.08,156.37 121.23,156.53 123.06,156.53 123.63,157.1 124.45,157.1
N17415515 on TOP (solid shape): outline of 97 points within 95.43,157.28 99.5,162.75
N18941770 on BOTTOM (solid shape): 121.98,133.03 121.98,131.89 121.72,131.89 121.72,132.71 121.53,132.91 120.58,132.91 120.26,132.59 120.26,132.4 119.69,132.4 119.69,132.91 120.26,133.48 121.53,133.48
N18941771 on BOTTOM (solid shape): 120.45,131.89 120.45,130.43 119.56,130.43 119.56,131.89 119.69,132.02 120.33,132.02
N18944130 on BOTTOM (solid shape): 67.95,38.98 67.95,38.3 67.43,37.78 67.43,37.15 67.37,37.08 66.86,37.08 66.8,37.15 66.8,37.72 67.49,38.42 67.49,38.8 67.75,39.05 67.87,39.05
N18944131 on BOTTOM (solid shape): 68.95,38.96 68.95,37.91 68.7,37.66 68.7,37.01 68.69,37 67.82,37 67.81,37.01 67.81,37.78 68.19,37.78 68.7,38.29 68.7,38.96 68.78,39.04 68.88,39.04
N18944132 on BOTTOM (solid shape): 68,36.39 68.7,36.39 68.7,35.62 68.64,35.56 67.76,35.56 67.13,36.19 66.83,36.19 66.81,36.22 66.81,36.7 66.85,36.74 67.65,36.74
N18944154 on BOTTOM (solid shape): 58.6,45.83 58.64,45.83 58.69,45.83 58.71,45.82 58.84,45.82 58.87,45.79 60.36,45.79 60.43,45.72 60.43,45.08 60.34,45 59.33,45 58.86,44.53 58.07,44.53 57.98,44.62 57.98,45.28 58.53,45.82 58.58,45.82
N18944155 on BOTTOM (solid shape): 61.44,45.69 61.44,44.48 61.36,44.4 61.36,43.54 61.29,43.47 60.61,43.47 60.56,43.51 60.56,44.48 61.17,45.08 61.17,45.73 61.22,45.78 61.35,45.78
N18944156 on BOTTOM (solid shape): 60,44.5 60,43.59 59.86,43.45 58.19,43.45 58.01,43.64 58.01,44.13 58.05,44.17 58.93,44.17 59.32,44.55 59.95,44.55
N18944237 on BOTTOM (solid shape): 62.41,45.73 62.41,45.62 62.69,45.35 63.12,45.35 63.36,45.11 63.5,45.11 63.56,45.1 63.62,45.11 64.36,45.11 64.47,45.11 64.52,45.06 64.52,44.56 64.47,44.51 63.46,44.51 63.26,44.72 62.47,44.72 62.14,45.05 62.14,45.2 62.14,45.2 62.14,45.74 62.2,45.8 62.35,45.8
N28483985 on TOP (solid shape): 130.1,176.66 130.1,176.15 130.23,176.02 130.87,176.02 130.99,175.89 130.99,174.5 130.87,174.37 127.69,174.37 127.31,174.75 127.31,176.4 127.82,176.91 129.85,176.91
N28484451 on TOP (solid shape): 132.39,173.86 134.3,173.86 134.42,173.74 134.42,172.47 134.3,172.34 131.4,172.34 131.15,172.59 131.15,173.99 131.27,174.12 132.14,174.12
N33124395 on TOP (solid shape): 58.32,19.78 58.32,18.58 58.22,18.48 58.22,16.95 56.06,16.95 56.06,17.59 56.7,17.59 57.71,18.61 57.84,18.61 58.13,18.89 58.13,19.75 58.19,19.81 58.29,19.81
N39282118 on BOTTOM (solid shape): 172.46,23.94 172.46,23.37 172.9,22.92 172.9,21.15 172.59,21.15 172.59,21.72 171.19,21.72 171.13,21.65 171.13,21.15 169.6,21.15 169.28,21.46 169.28,23.94 169.35,24 172.4,24
N39282176 on BOTTOM (solid shape): 169.28,31.88 169.28,30.1 169.22,30.04 167.57,30.04 167.57,31.05 168.33,31.05 168.59,31.31 168.59,32 169.16,32
N39854666 on TOP (solid shape): 31.68,71.12 31.68,69.98 31.43,69.72 30.54,69.72 30.28,69.98 30.28,70.87 29.65,71.5 27.74,71.5 26.22,69.98 25.2,69.98 24.44,69.21 20.88,69.21 20.5,69.6 20.5,71.12 20.76,71.37 21.77,71.37 22.66,70.48 23.42,70.48 24.44,71.5 25.71,71.5 26.85,72.64 30.16,72.64
N39880170 on BOTTOM (solid shape): 38.86,56.2 38.66,56.01 38.66,54.36 38.41,54.1 37.65,54.1 37.59,54.17 37.59,54.29 37.65,54.36 38.16,54.36 38.22,54.42 38.22,57.09 38.86,57.09
N39880453 on BOTTOM (solid shape): 41.27,57.66 40.57,56.96 39.24,56.96 39.24,57.47 39.87,57.47 40.25,57.85 40.25,59.63 41.27,59.63
N40185793 on TOP (solid shape): outline of 99 points within 71.68,165.2 77.91,170.94
N40185849 on BOTTOM (solid shape): 116.77,157.62 116.77,155.96 116.78,155.95 116.78,155.9 116.66,155.78 115.99,155.78 115.97,155.81 115.97,156.65 115.74,156.87 115.74,157.65 115.87,157.77 116.62,157.77
N40185889 on TOP (solid shape): 133.28,157.99 133.28,156.18 132.58,155.48 131.79,155.48 131.66,155.61 131.66,157.96 131.88,158.18 133.09,158.18
N40185889 on BOTTOM (solid shape): 111.89,156.56 112.56,156.56 112.74,156.38 112.74,156.12 112.61,155.99 111.47,155.99 111.27,156.19 111.27,156.95 111.31,156.99 111.46,156.99
N40185889 on IN1 (solid shape): 116.26,155.77 111.63,155.77 111.37,156.02 111.37,156.59 111.56,156.78 116.26,156.78
N40185889 on IN1 (solid shape): 132.84,157.92 132.84,156.84 131.76,155.77 130.49,155.77 130.49,156.78 131.12,156.78 131.63,157.29 131.63,157.92 131.76,158.05 132.71,158.05
N40185891 on TOP (solid shape): 121.02,158.11 121.02,157.42 120.9,157.29 120.33,157.29 119.82,156.78 119.06,156.78 118.99,156.84 118.99,158.05 119.18,158.24 120.9,158.24
N40185897 on BOTTOM (solid shape): 113.33,156.71 115.21,156.71 115.27,156.65 115.27,155.79 115.22,155.75 113.58,155.75 112.61,156.71 112.05,156.71 111.6,157.17 111.6,157.31 111.64,157.35 112.68,157.35
N40185902 on TOP (solid shape): outline of 631 points within 71.56,151.7 113.85,176.15
N40185902 on BOTTOM (solid shape): 113.85,154.43 113.85,153.73 112.32,153.73 112.32,153.1 113.85,153.1 113.85,151.89 113.59,151.64 111.18,151.64 110.55,152.27 110.55,153.29 111.75,154.5 113.79,154.5
N40185955 on BOTTOM (solid shape): 130.87,162.37 130.87,160.85 129.34,160.85 129.34,160.21 130.87,160.21 130.87,158.24 131.18,157.92 131.18,157.92 131.47,157.64 131.47,156.22 131.28,156.03 127.87,156.03 126.8,157.1 126.8,158.56 126.23,159.13 125.34,159.13 125.34,162.56 125.41,162.62 130.61,162.62
N40186030 on TOP (solid shape): 126.74,163.13 126.74,162.5 126.68,162.43 124.39,162.43 124.33,162.5 124.33,164.15 125.72,164.15
N40197882 on BOTTOM (solid shape): 166.11,108.84 165.86,108.58 165.86,107.89 165.79,107.82 165.35,107.82 165.28,107.89 165.28,108.7 165.42,108.84 165.42,109.69 165.46,109.73 166.11,109.73
N40197981 on BOTTOM (solid shape): 166.05,105.28 166.05,103.31 165.41,103.31 165.41,105.28 165.47,105.35 165.98,105.35
N40198029 on BOTTOM (solid shape): 160.89,104.95 160.89,103.42 161.15,103.16 161.15,102.3 161.13,102.28 160.55,102.28 160.49,102.33 160.49,102.85 160.28,103.06 160.3,103.27 160.21,103.45 160.21,104.93 160.26,104.98 160.85,104.98
N40598492 on BOTTOM (solid shape): 47.68,36.36 48.92,36.36 48.97,36.31 48.97,35.42 48.94,35.4 47.08,35.4 46.1,36.39 46.03,36.45 46.03,37.27 46.09,37.34 46.7,37.34
N40598500 on BOTTOM (solid shape): 40.7,36.19 40.63,36.13 40.13,36.13 40,36.26 40,38.1 40.06,38.16 40.7,38.16
N41455626 on BOTTOM (solid shape): 72.17,24.33 72.17,21.72 72.12,21.67 71.41,21.67 71.35,21.72 71.35,22.3 71.18,22.48 70.92,22.48 70.8,22.61 70.8,24.26 70.92,24.38 72.12,24.38

Small or netless copper shapes (teardrops, artwork), in the pictures only: 245 on TOP, 27 on BOTTOM, 1 on IN2

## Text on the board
Ref Des/Silkscreen Bottom: HGPU1 | HGPU3 | HGPU2 | F5203:1.1A/24V | F5201:1.1A/24V | DIMM B | DIMM A | SODIMM-ONLY SUPPORT DDR4 | M2X3L
User.Comments: LA-D871P | 2017-08-01 | 2016-08-01 | BAL60 | Minjia | REV:1.0(A00) | VCC_CORE | 1D05V_S0 | VGA_CORE | AUD_AGND | 1D35V_VGD_S0
USER_PART_NUM_BOTTOM: 109.11 | 165.27 | 46.40 | 0.00 | 19.09 | 20.70 | 38.09 | 13.42 | 56.46 | 100.35 | 25.87 | 7.54 | 59.11 | 44.87 | 65.60 | 173.09 | 118.00 | 102.65 | 71.90 | 13.52 | 98.69 | 57.50 | 53.69 | 50.65 | 153.50 | 57.30
DEVICE_TYPE_BOTTOM: TP
USER_PART_NUM_TOP: 3.00 | 3.80 | {\Fgdt;n}\Ftxt;3.00 | {\Fgdt;n}\Ftxt;8.90 | {\Fgdt;n}\Ftxt;3.70 | {\Fgdt;n}\Ftxt;6.50 | {\Fgdt;n}\Ftxt;3.40 | {\Fgdt;n}\Ftxt;3.20 | {\Fgdt;n}\Ftxt;6.90 | {\Fgdt;n}\Ftxt;4.00 | {\Fgdt;n}\Ftxt;7.50 | {\Fgdt;n}\Ftxt;3.30 | {\Fgdt;n}\Ftxt;4.50
COMPVAL_TYPE_TOP: 160.65 | 138.79 | 114.54 | 7.86 | 0.61 | 122.77 | 94.90 | 105.21 | 151.74 | 136.27 | 59.69 | 56.43 | 53.75 | 39.26 | 0.00 | 26.57 | 50.32 | 144.40 | 4.51 | 19.09 | 6.97 | 16.52 | 28.83 | 35.93 | 37.15 | 49.36 | 57.40 | 66.71 | 66.30 | 24.8\Fgdt;{\Fgdt;~} | 119.73 | 124.65 | 92.90 | 169.69 | 68.50 | 56.58 | 9.33 | 48.38 | 41.76 | 18.26 | 8.70 | 18.93 | 90.99 | 23.75 | 24.84 | 34.16 | 112.24 | 47.60 | 56.85 | 158.80 | 20.41 | 29.95 | 126.30 | 141.63 | 25.87 | 85.15 | 16.57 | 60.98 | 44.87
COMPVAL_TYPE_BOTTOM: TP
PAGE_OUTLINE: {\Fgdt;n}\Ftxt;6.50 | {\Fgdt;n}\Ftxt;6.90 | {\Fgdt;n}\Ftxt;7.50 | 4.88 | 6.10 | 5.90 | 7.90
User.30: FIGURE | SIZE | 8.0 | 22.0 | 24.0 | 28.0 | 35.0 | 39.0 | 118.0 | 126.0 | 130.0 | 134.0 | 146.0 | 31.0 | 43.0 | 47.0 | 55.0 | 63.0 | 67.0 | 157.0 | 63.0x28.0 | 67.0x35.0 | 94.0x28.0 | 94.0x35.0 | 112.0x31.0 | 134.0x24.0 | 150.0x118.0 | DRILL CHART: TOP to BOTTOM | ALL UNITS ARE IN MILS | TOLERANCE | +3.0/-3.0 | +2.0/-2.0 | PLATED | NON-PLATED | QTY | 353 | 5453 | 19 | 15 | 9 | 8 | 5 | 2 | 3 | 1 | 4
User.31: 10.4mil | 8.5mil | 6.5mil | 5mil | trace Width | 4 | 5 | 4.4/3.5 | 3.9/3.5 | 4/3.5 | 3.6/3.5 | 5/5.1 | Width/space | 3.5/8.2 | L5-GND | 100 ohm
